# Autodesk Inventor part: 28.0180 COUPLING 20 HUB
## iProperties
Created: 2007-06
Part Number: 28.0180 COUPLING 20 HUB
Material: Steel
Document SubType Name: Modeling
Designer: Andy Moles
Mass: 290.562 g
Surface Area: 119.016 cm^2
Volume: 37.0143 cm^3
Density: 7.85 g/cm^3
Author: Andy Moles
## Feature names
1. Base1
